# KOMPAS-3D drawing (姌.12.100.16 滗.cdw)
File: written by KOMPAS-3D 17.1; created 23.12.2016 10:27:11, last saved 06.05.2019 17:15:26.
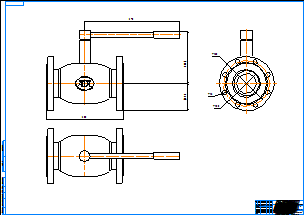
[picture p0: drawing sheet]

Sheet 1: A0, landscape

Title block, sheet 1: name: КШ.12.100.16 фф; material: Внимание! Данный продукт является объектом авторского права ООО «Торговый Дом АДЛ». / Запрещается изменение, копирование, распространение / (в том числе путем копирования на другие сайты и ресурсы в Интернете) / или любое иное использование информации и объектов без предварительного / согласия правообладателя (ООО «Торговый Дом АДЛ»).; sheets: 1; organisation: ООО "Торговый дом АДЛ"; sheet format: A0; stored path: C:\Users\tra\Desktop\2д чертежи\Шаровые краны БИВАЛ\КШ_Бивал_серия_11_12\KOMPAS_2D\КШ.12.100.16 фф.cdw

Views: Вид 1, Проекционный вид 2, Проекционный вид 3
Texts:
  Klimkovich
  ADL
Dimensions and other numbers on the sheet: 300; 370; 205,1; 107,5; 180; 100; 18; 1:1; 1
